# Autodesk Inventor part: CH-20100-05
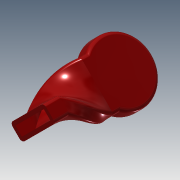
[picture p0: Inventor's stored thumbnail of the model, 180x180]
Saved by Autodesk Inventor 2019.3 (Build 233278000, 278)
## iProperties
Created: 2012-09
Part Number: CH-20100-05
Material: Ogólny
Document SubType Name: Modeling
Designer: CADENGINEERING4
Density: 1 g/cm^3
Appearance: Czerwona
Author: CADENGINEERING4
Revision Number: ÈÎºÎ
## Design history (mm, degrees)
feature "³é¿Ç2"
node "Bryła1"
